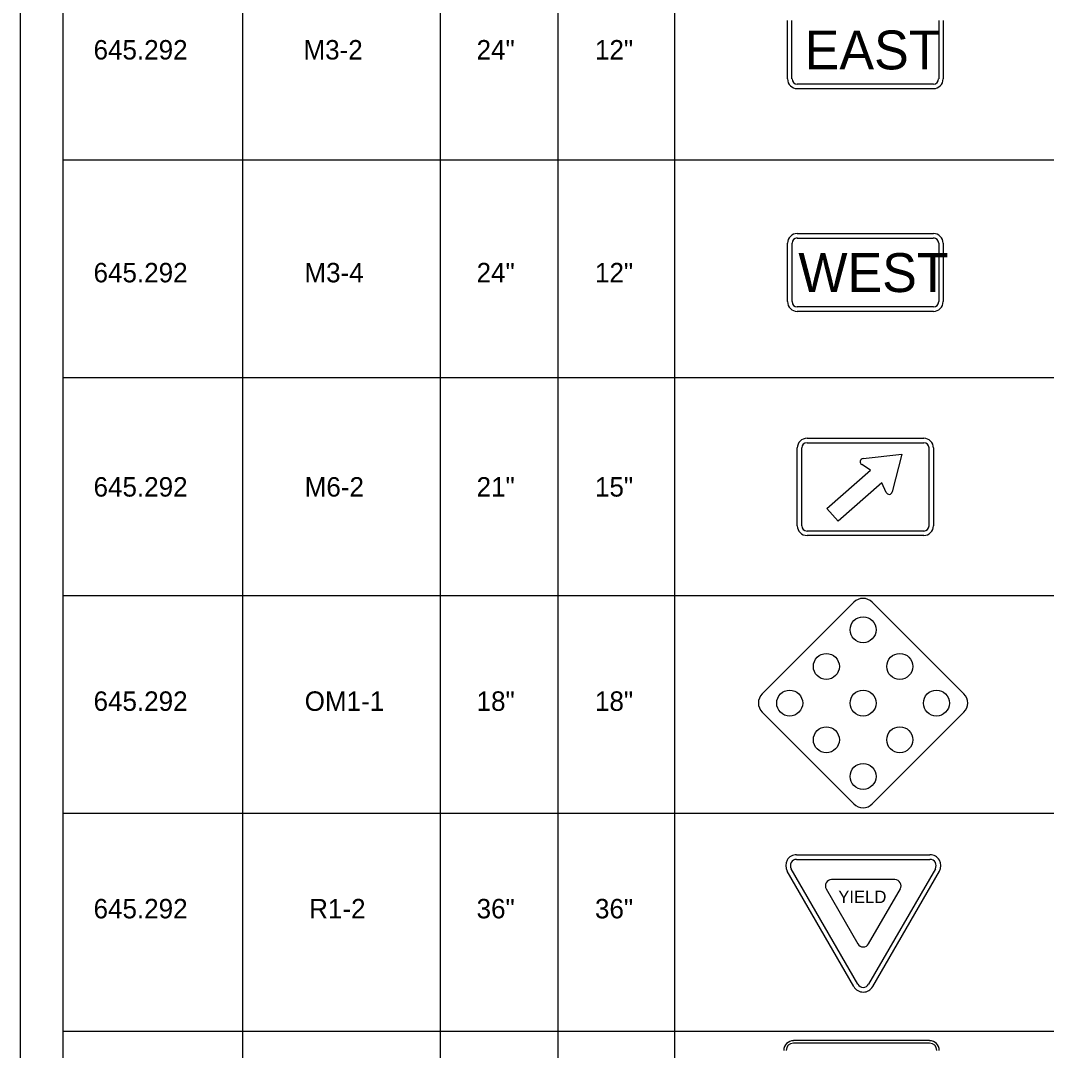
# Model space of a CAD drawing. Extents: x 914742 to 915492, y 328736 to 329423.
# Drawn here: x 914741.7 to 914906.5, y 329093.4 to 329258.9 of the extents above; entities that cross this region are included whole.
import ezdxf

# ---------------------------------------------------------------- set-up
doc = ezdxf.new("R2010")
doc.units = 0
for name, color, linetype in [('ANNOTATION', 7, 'Continuous'), ('Default', 7, 'Continuous'), ('ObjectMarker', 7, 'Continuous'), ('PLOT BOUNDARY', 7, 'Continuous'), ('SignPanel', 7, 'Continuous'), ('SIGNSUM-TABLE', 7, 'Continuous')]:
    doc.layers.add(name, color=color, linetype=linetype)

# ---------------------------------------------------------------- blocks, each defined once
blk = doc.blocks.new('OM1-1')
at = {"layer": 'ObjectMarker'}
for p, q in [((-0.0295, 0.6776), (-0.3241, 0.383)), ((0.3241, 0.383), (0.0295, 0.6776)), ((-0.3241, 0.3241), (-0.0295, 0.0295)), ((0.0295, 0.0295), (0.3241, 0.3241))]:
    blk.add_line(p, q, dxfattribs=at)
for centre in [(0, 0.5893), (-0.1179, 0.4714), (0.1179, 0.4714), (-0.2357, 0.3536), (0, 0.3536), (0.2357, 0.3536), (-0.1179, 0.2357), (0.1179, 0.2357), (0, 0.1179)]:
    blk.add_circle(centre, 0.0417, dxfattribs=at)
for centre, start, end in [((0, 0.6482), 45, 135), ((-0.2946, 0.3536), 135, 225), ((0.2946, 0.3536), 315, 45), ((0, 0.0589), 225, 315)]:
    blk.add_arc(centre, 0.0417, start, end, dxfattribs=at)

msp = doc.modelspace()

# ---------------------------------------------------------------- linework, layer by layer
at = {"layer": 'PLOT BOUNDARY'}
msp.add_lwpolyline([(915491.67, 328898.32), (914741.67, 328898.32), (914741.67, 329423.32), (915491.67, 329423.32)], close=True, dxfattribs=at)
msp.add_lwpolyline([(914741.67, 328925.96), (914741.67, 329423.32), (915491.67, 329423.32), (915491.67, 328925.96)], dxfattribs=at)
at = {"layer": 'SignPanel'}
for p, q in [((914877.02, 329188.52), (914883.25, 329189.26)), ((914883.25, 329189.26), (914881.7, 329183.17)), ((914878.22, 329186.66), (914876.8, 329187.56)), ((914871.22, 329180.52), (914878.22, 329186.66)), ((914880.03, 329184.61), (914873.02, 329178.46)), ((914880.73, 329183.08), (914880.03, 329184.61)), ((914873.02, 329178.46), (914871.22, 329180.52)), ((914866.34, 329124.87), (914887.77, 329124.87)), ((914876.19, 329104.05), (914865.47, 329122.62)), ((914866.34, 329124.12), (914887.77, 329124.12)), ((914888.64, 329122.62), (914877.92, 329104.05)), ((914875.54, 329103.67), (914864.82, 329122.24)), ((914878.57, 329103.67), (914889.29, 329122.24)), ((914871.1, 329119.37), (914876.19, 329110.55)), ((914882.14, 329120.87), (914871.96, 329120.87)), ((914877.92, 329110.55), (914883.01, 329119.37)), ((914887.71, 329094.99), (914865.84, 329094.99)), ((914887.71, 329094.6), (914865.84, 329094.6))]:
    msp.add_line(p, q, dxfattribs=at)
for points in [[(914864.88, 329249.54), (914864.88, 329258.91)], [(914865.6, 329249.54), (914865.6, 329258.91)], [(914889.17, 329258.91), (914889.17, 329249.54)], [(914889.88, 329258.91), (914889.88, 329249.54)], [(914888.32, 329248.69), (914866.45, 329248.69)], [(914888.32, 329247.97), (914866.45, 329247.97)], [(914866.45, 329224.69), (914888.33, 329224.69)], [(914866.45, 329223.97), (914888.33, 329223.97)], [(914864.89, 329213.75), (914864.89, 329223.13)], [(914865.61, 329213.75), (914865.61, 329223.13)], [(914889.17, 329223.13), (914889.17, 329213.75)], [(914889.89, 329223.13), (914889.89, 329213.75)], [(914888.33, 329212.91), (914866.45, 329212.91)], [(914888.33, 329212.19), (914866.45, 329212.19)], [(914868.02, 329191.79), (914886.77, 329191.79)], [(914868.02, 329191.08), (914886.77, 329191.08)], [(914866.45, 329177.73), (914866.45, 329190.23)], [(914867.17, 329177.73), (914867.17, 329190.23)], [(914887.61, 329190.23), (914887.61, 329177.73)], [(914888.33, 329190.23), (914888.33, 329177.73)], [(914886.77, 329176.89), (914868.02, 329176.89)], [(914886.77, 329176.17), (914868.02, 329176.17)]]:
    msp.add_lwpolyline(points, dxfattribs=at)
for centre, radius, start, end in [((914866.45, 329249.54), 1.56, 180, 270), ((914866.45, 329249.54), 0.846, 180, 270), ((914888.32, 329249.54), 1.56, 270, 0), ((914888.32, 329249.54), 0.846, 270, 0), ((914866.45, 329223.13), 1.56, 90, 180), ((914866.45, 329223.13), 0.846, 90, 180), ((914888.33, 329223.13), 1.56, 360, 90), ((914888.33, 329223.13), 0.846, 360, 90), ((914866.45, 329213.75), 1.56, 180, 270), ((914866.45, 329213.75), 0.846, 180, 270), ((914888.33, 329213.75), 1.56, 270, 0), ((914888.33, 329213.75), 0.846, 270, 0), ((914868.02, 329190.23), 1.56, 90, 180), ((914868.02, 329190.23), 0.846, 90, 180), ((914886.77, 329190.23), 1.56, 360, 90), ((914886.77, 329190.23), 0.846, 360, 90), ((914877.08, 329188), 0.521, 96.7689, 237.9013), ((914881.2, 329183.3), 0.521, 204.6127, 345.7451), ((914868.02, 329177.73), 1.56, 180, 270), ((914868.02, 329177.73), 0.846, 180, 270), ((914886.77, 329177.73), 1.56, 270, 0), ((914886.77, 329177.73), 0.846, 270, 0), ((914866.34, 329123.12), 1.75, 90, 210), ((914887.77, 329123.12), 1.75, 330, 90), ((914866.34, 329123.12), 1, 90, 210), ((914887.77, 329123.12), 1, 330, 90), ((914871.96, 329119.87), 1, 90, 210), ((914882.14, 329119.87), 1, 330, 90), ((914877.05, 329111.05), 1, 210, 330), ((914877.05, 329104.55), 1.75, 210, 330), ((914877.05, 329104.55), 1, 210, 330), ((914865.84, 329093.42), 1.56, 90, 180), ((914865.84, 329093.42), 1.17, 90, 180), ((914887.71, 329093.42), 1.56, 360, 90), ((914887.71, 329093.42), 1.17, 360, 90)]:
    msp.add_arc(centre, radius, start, end, dxfattribs=at)
at = {"layer": 'SIGNSUM-TABLE'}
for p, q in [((914748.46, 329404.01), (914748.46, 328925.96)), ((914748.46, 329404.01), (914748.46, 328925.96)), ((914777.33, 329404.01), (914777.33, 328925.96)), ((914777.33, 329404.01), (914777.33, 328925.96)), ((914809.12, 328925.96), (914809.12, 329404.01)), ((914809.12, 328925.96), (914809.12, 329404.01)), ((914846.79, 328925.96), (914846.79, 329404.01)), ((914846.79, 328925.96), (914846.79, 329404.01)), ((914827.96, 329390.27), (914827.96, 328925.96)), ((914827.96, 329390.27), (914827.96, 328925.96)), ((914748.46, 329236.54), (915109.88, 329236.54)), ((914748.46, 329236.54), (915109.88, 329236.54)), ((914748.46, 329201.54), (915109.88, 329201.54)), ((914748.46, 329201.54), (915109.88, 329201.54)), ((914748.46, 329166.54), (915109.88, 329166.54)), ((914748.46, 329166.54), (915109.88, 329166.54)), ((914748.46, 329131.54), (915109.88, 329131.54)), ((914748.46, 329096.54), (915109.88, 329096.54)), ((914748.46, 329096.54), (915109.88, 329096.54))]:
    msp.add_line(p, q, dxfattribs=at)

# ---------------------------------------------------------------- block references
at = {"layer": 'Default', "xscale": 50, "yscale": 50}
msp.add_blockref('OM1-1', (914877.02, 329131.56), dxfattribs=at)

# ---------------------------------------------------------------- texts
at = {"layer": 'ANNOTATION'}
for s, p in [('645.292', (914753.39, 329252.66)), ('M3-2', (914787.12, 329252.66)), ('24"', (914814.93, 329252.66)), ('12"', (914833.95, 329252.66)), ('645.292', (914753.39, 329216.85)), ('M3-4', (914787.27, 329216.85)), ('24"', (914814.93, 329216.85)), ('12"', (914833.95, 329216.85)), ('645.292', (914753.39, 329182.42)), ('M6-2', (914787.31, 329182.42)), ('21"', (914814.93, 329182.42)), ('15"', (914833.95, 329182.42)), ('645.292', (914753.39, 329147.99)), ('OM1-1', (914787.31, 329147.99)), ('18"', (914814.93, 329147.99)), ('18"', (914833.95, 329147.99)), ('645.292', (914753.39, 329114.64)), ('R1-2', (914788.03, 329114.64)), ('36"', (914814.93, 329114.64)), ('36"', (914833.95, 329114.64))]:
    msp.add_text(s, height=3.125, dxfattribs=at).set_placement(p)
at = {"layer": 'SignPanel'}
for s, height, p in [('EAST', 6.25, (914867.64, 329251.07)), ('WEST', 6.25, (914866.63, 329215.29)), ('YIELD', 2, (914873.04, 329117.1))]:
    msp.add_text(s, height=height, dxfattribs=at).set_placement(p)

doc.saveas('drawing.dxf')
